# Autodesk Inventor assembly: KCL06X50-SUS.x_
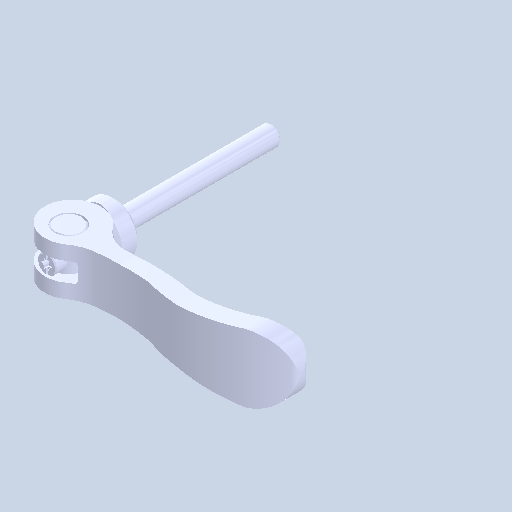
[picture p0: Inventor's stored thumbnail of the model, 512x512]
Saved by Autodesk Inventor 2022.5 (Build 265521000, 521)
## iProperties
Created: 2024-08
Part Number: KCL06X50-SUS.x_
Document SubType Name: Assembly
Designer: ImaoCorp
Author: ImaoCorp
Sending System: SOLIDWORKS 2022-2022290
MC: AMD64
MC_MODEL: Intel64 Family 6 Model 60 Stepping 3, GenuineIntel
OS: Windows_NT
FRU: Parasolid Version 33.1, build 260,  4-25-2022
FORMAT: text
GUISE: transmit
KEY: FILEKCL06X50-SUS.x_t
DATE: Thu Aug 29 10:50:07 2024
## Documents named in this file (5)
- Y:\5.更新分\2024年対応\1001_KCL\データ\kcl06x50-sus\KCL06X50-SUS.x_.iam
- Y:\5.更新分\2024年対応\1001_KCL\データ\kcl06x50-sus\KCL06X50-SUS_01.ipt
- Y:\5.更新分\2024年対応\1001_KCL\データ\kcl06x50-sus\KCL06X50-SUS_02.ipt
- Y:\5.更新分\2024年対応\1001_KCL\データ\kcl06x50-sus\KCL06X50-SUS_03.ipt
- Y:\5.更新分\2024年対応\1001_KCL\データ\kcl06x50-sus\KCL06X50-SUS_04.ipt
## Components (4 placed, 4 different names)
1. KCL06X50-SUS_01
2. KCL06X50-SUS_02
3. KCL06X50-SUS_03
4. KCL06X50-SUS_04
